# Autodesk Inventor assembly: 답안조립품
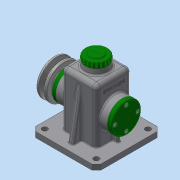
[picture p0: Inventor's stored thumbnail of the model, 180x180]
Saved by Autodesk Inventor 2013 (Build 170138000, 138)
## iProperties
Created: 2018-10
Part Number: 답안조립품
Document SubType Name: Assembly
Designer: Administrator
Author: Administrator
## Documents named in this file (14)
- C:\Users\Administrator\Desktop\481013V1001\답안조립품.iam
- C:\Users\Administrator\Desktop\481013V1001\본체.ipt
- C:\Users\Administrator\Desktop\481013V1001\V-벨트풀리.ipt
- C:\Users\Administrator\Desktop\481013V1001\뒤커버.ipt
- C:\Users\Administrator\Desktop\481013V1001\멈춤링 15 x 1.ipt
- C:\Users\Administrator\Desktop\481013V1001\베어링 15 x 35 x 11.ipt
- C:\Users\Administrator\Desktop\481013V1001\볼트 M4 x 10.ipt
- C:\Users\Administrator\Desktop\481013V1001\볼트 M6 x 12.ipt
- C:\Users\Administrator\Desktop\481013V1001\상부캡.ipt
- C:\Users\Administrator\Desktop\481013V1001\앞커버.ipt
- C:\Users\Administrator\Desktop\481013V1001\오일실 15 25 7.ipt
- C:\Users\Administrator\Desktop\481013V1001\와셔.ipt
- C:\Users\Administrator\Desktop\481013V1001\축.ipt
- C:\Users\Administrator\Desktop\481013V1001\키 5 x 5 x 14.ipt
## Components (1 placed, 1 different names)
1. V-벨트풀리:1 — 플러쉬:1
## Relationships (1: Flush 1)
- 플러쉬:1 [Flush]: V-벨트풀리:1
